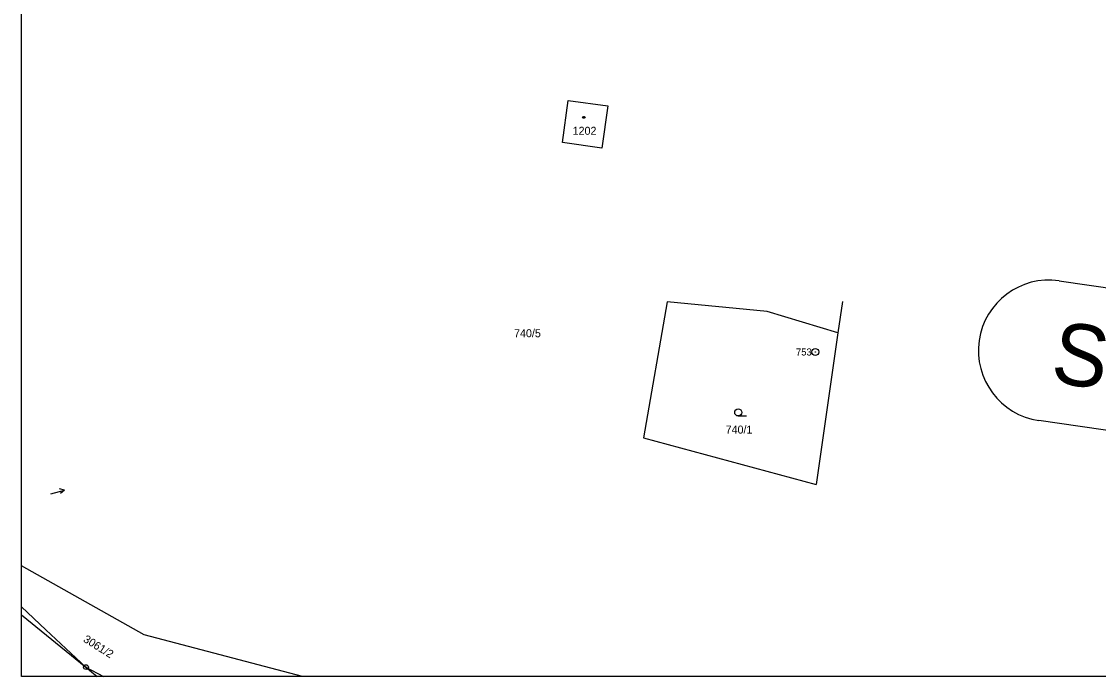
# Model space of a CAD drawing. Extents: x -728802 to -728097, y -1073200 to -1072700.
# Drawn here: x -728800 to -728571.2, y -1073200 to -1073061 of the extents above; entities that cross this region are included whole.
import ezdxf

# ---------------------------------------------------------------- set-up
doc = ezdxf.new("R2010")
doc.units = 0
for name, color, linetype in [('Hranice parcel', 7, 'Continuous'), ('K_31_listy_JŽM', 7, 'Continuous'), ('Pop  PČ popisy', 7, 'Continuous'), ('ZZZ_popisky', 7, 'Continuous')]:
    doc.layers.add(name, color=color, linetype=linetype)

msp = doc.modelspace()

# ---------------------------------------------------------------- linework, layer by layer
at = {"layer": 'Hranice parcel'}
for p, q in [((-728662.87, -1073120.46), (-728667.89, -1073149.35)), ((-728641.62, -1073122.5), (-728662.87, -1073120.46)), ((-728625.65, -1073120.4), (-728626.6, -1073127.02)), ((-728626.6, -1073127.02), (-728641.62, -1073122.5)), ((-728626.6, -1073127.02), (-728631.24, -1073159.26)), ((-728647.77, -1073144.7), (-728646.02, -1073144.7)), ((-728667.89, -1073149.35), (-728631.24, -1073159.26)), ((-728786.31, -1073198.02), (-728782.58, -1073200))]:
    msp.add_line(p, q, dxfattribs=at)
for points in [[(-728683.88, -1073077.73), (-728675.45, -1073078.83), (-728676.72, -1073087.83), (-728685.08, -1073086.63), (-728683.88, -1073077.73)], [(-728740.33, -1073200), (-728773.98, -1073191.19), (-728800, -1073176.52)], [(-728800, -1073185.2), (-728794.83, -1073190.07), (-728786.31, -1073198.02)], [(-728800, -1073186.91), (-728786.31, -1073198.02)], [(-728786.31, -1073198.02), (-728783.95, -1073200)]]:
    msp.add_lwpolyline(points, dxfattribs=at)
for centre, radius in [((-728680.64, -1073081.32), 0.175), ((-728680.44, -1073081.31), 0.175), ((-728631.4, -1073131.11), 0.75), ((-728631.4, -1073131.11), 0.03), ((-728647.77, -1073143.95), 0.75), ((-728786.31, -1073198.02), 0.5), ((-728786.31, -1073198.02), 0.0303)]:
    msp.add_circle(centre, radius, dxfattribs=at)
at = {"layer": 'K_31_listy_JŽM'}
msp.add_lwpolyline([(-728800, -1073200), (-728800, -1072700), (-728100, -1072700), (-728100, -1073200), (-728800, -1073200)], dxfattribs=at)
at = {"layer": 'Pop  PČ popisy'}
for p, q in [((-728793.76, -1073161.2), (-728790.86, -1073160.42)), ((-728790.86, -1073160.42), (-728791.96, -1073160.2)), ((-728790.86, -1073160.42), (-728791.7, -1073161.17))]:
    msp.add_line(p, q, dxfattribs=at)
at = {"layer": 'ZZZ_popisky'}
for points in [[(-728579.59, -1073115.98), (-728527.63, -1073123.5)], [(-728479.97, -1073160.71), (-728583.89, -1073145.67)]]:
    msp.add_lwpolyline(points, dxfattribs=at)
msp.add_arc((-728581.74, -1073130.83), 15, 81.7647, 261.7647, dxfattribs=at)

# ---------------------------------------------------------------- texts
at = {"layer": 'Hranice parcel'}
for s, height, p in [('1202', 1.7, (-728682.94, -1073085)), ('740/5', 1.7, (-728695.38, -1073127.98)), ('753', 1.5, (-728635.5, -1073131.86)), ('740/1', 1.7, (-728650.44, -1073148.44))]:
    msp.add_text(s, height=height, dxfattribs=at).set_placement(p)
msp.add_text('3061/2', height=1.7, rotation=328, dxfattribs=at).set_placement((-728787.04, -1073192.52))
at = {"layer": 'ZZZ_popisky'}
msp.add_text('SO 11-30-02', height=13.125, rotation=351.7647, dxfattribs=at).set_placement((-728581.7, -1073137.46))

doc.saveas('drawing.dxf')
